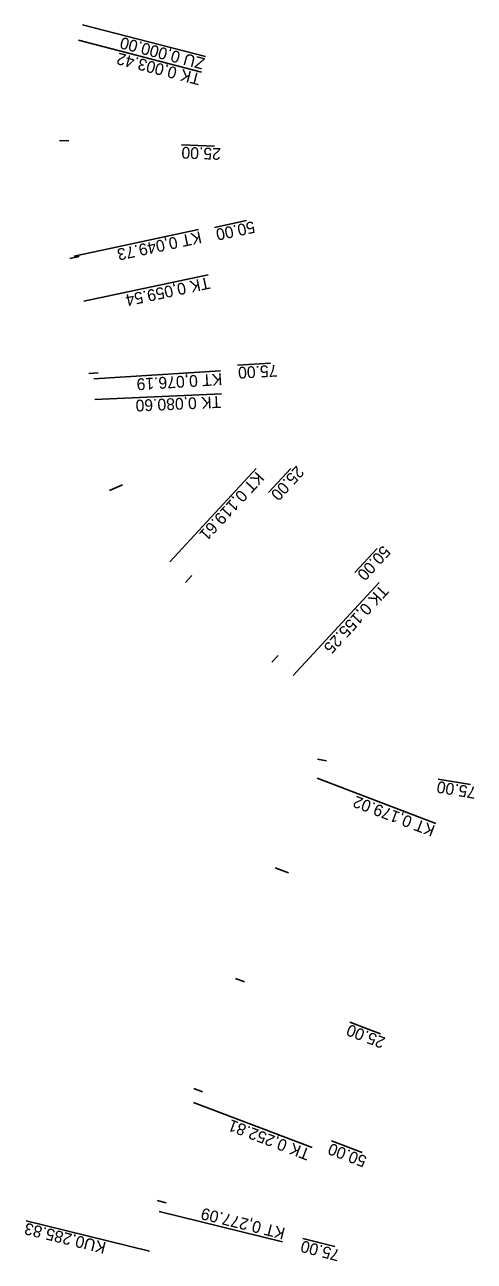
# Model space of a CAD drawing. Extents: x -574342 to -507939, y -1144044 to -1123894.
# Drawn here: x -574342.4 to -574246.9, y -1124157.1 to -1123894.2 of the extents above; entities that cross this region are included whole.
import ezdxf

# ---------------------------------------------------------------- set-up
doc = ezdxf.new("R2010")
doc.units = 0
doc.layers.add('C14b staníčení', color=7, linetype='Continuous')

msp = doc.modelspace()

# ---------------------------------------------------------------- linework, layer by layer
at = {"layer": 'C14b staníčení'}
for points in [[(-574330.12, -1123894.19), (-574303.97, -1123900.93)], [(-574330.97, -1123897.5), (-574304.82, -1123904.24)], [(-574333.07, -1123918.85), (-574335.07, -1123918.78)], [(-574302.09, -1123919.98), (-574309.09, -1123919.73)], [(-574295.26, -1123935.82), (-574302.11, -1123937.29)], [(-574331.93, -1123943.39), (-574305.52, -1123937.74)], [(-574330.89, -1123943.44), (-574332.85, -1123943.86)], [(-574329.87, -1123952.98), (-574303.47, -1123947.34)], [(-574290.22, -1123966.17), (-574297.21, -1123966.57)], [(-574326.82, -1123968.23), (-574328.82, -1123968.34)], [(-574327.76, -1123969.48), (-574300.81, -1123967.81)], [(-574327.56, -1123973.88), (-574300.59, -1123972.69)], [(-574311.56, -1124008.38), (-574293.23, -1123988.55)], [(-574285.88, -1123988.54), (-574290.63, -1123993.68)], [(-574321.65, -1123991.99), (-574324.38, -1123993.24)], [(-574267.52, -1124005.52), (-574272.27, -1124010.66)], [(-574306.92, -1124011.3), (-574308.28, -1124012.77)], [(-574285.4, -1124032.57), (-574267.06, -1124012.75)], [(-574288.57, -1124028.28), (-574289.93, -1124029.75)], [(-574278.26, -1124050.67), (-574280.23, -1124050.35)], [(-574280.29, -1124054.38), (-574255.06, -1124064)], [(-574247.67, -1124055.71), (-574254.57, -1124054.57)], [(-574286.36, -1124074.52), (-574289.16, -1124073.45)], [(-574295.73, -1124097.7), (-574297.6, -1124096.99)], [(-574266.77, -1124108.75), (-574273.31, -1124106.25)], [(-574304.64, -1124121.06), (-574306.51, -1124120.35)], [(-574306.57, -1124123.33), (-574281.35, -1124132.95)], [(-574270.69, -1124134), (-574277.23, -1124131.51)], [(-574312.35, -1124144.71), (-574314.28, -1124144.21)], [(-574313.83, -1124146.49), (-574287.62, -1124152.98)], [(-574315.93, -1124154.97), (-574342.14, -1124148.48)], [(-574276.53, -1124153.99), (-574283.31, -1124152.23)]]:
    msp.add_lwpolyline(points, dxfattribs=at)

# ---------------------------------------------------------------- texts
for s, rotation, p in [('ZU 0,000.00', 165.5366, (-574303.96, -1123901.34)), ('TK 0,003.42', 165.5366, (-574304.85, -1123904.65)), ('25.00', 177.9037, (-574300.7, -1123920.44)), ('50.00', 192.0754, (-574293.8, -1123935.92)), ('KT 0,049.73', 192.0754, (-574305.15, -1123938.1)), ('TK 0,059.54', 192.0754, (-574303.37, -1123947.82)), ('75.00', 183.2196, (-574288.79, -1123966.49)), ('KT 0,076.19', 183.5345, (-574300.53, -1123968.3)), ('TK 0,080.60', 182.5362, (-574300.72, -1123973.14)), ('25.00', 227.2365, (-574284.63, -1123987.78)), ('KT 0,119.61', 227.2365, (-574293.15, -1123989.05)), ('50.00', 227.2365, (-574266.27, -1124004.76)), ('TK 0,155.25', 227.2365, (-574266.7, -1124013.09)), ('75.00', 170.6478, (-574246.34, -1124056.33)), ('KT 0,179.02', 159.1305, (-574255, -1124064.56)), ('25.00', 159.1305, (-574265.59, -1124109.62)), ('TK 0,252.81', 159.1305, (-574281.55, -1124133.38)), ('50.00', 159.1305, (-574269.52, -1124134.88)), ('KT 0,277.09', 166.0866, (-574286.9, -1124150.07)), ('KU0,285.83', 166.0866, (-574324.97, -1124153.13)), ('75.00', 165.4877, (-574275.27, -1124154.73))]:
    msp.add_text(s, height=2.5, rotation=rotation, dxfattribs=at).set_placement(p)

doc.saveas('drawing.dxf')
